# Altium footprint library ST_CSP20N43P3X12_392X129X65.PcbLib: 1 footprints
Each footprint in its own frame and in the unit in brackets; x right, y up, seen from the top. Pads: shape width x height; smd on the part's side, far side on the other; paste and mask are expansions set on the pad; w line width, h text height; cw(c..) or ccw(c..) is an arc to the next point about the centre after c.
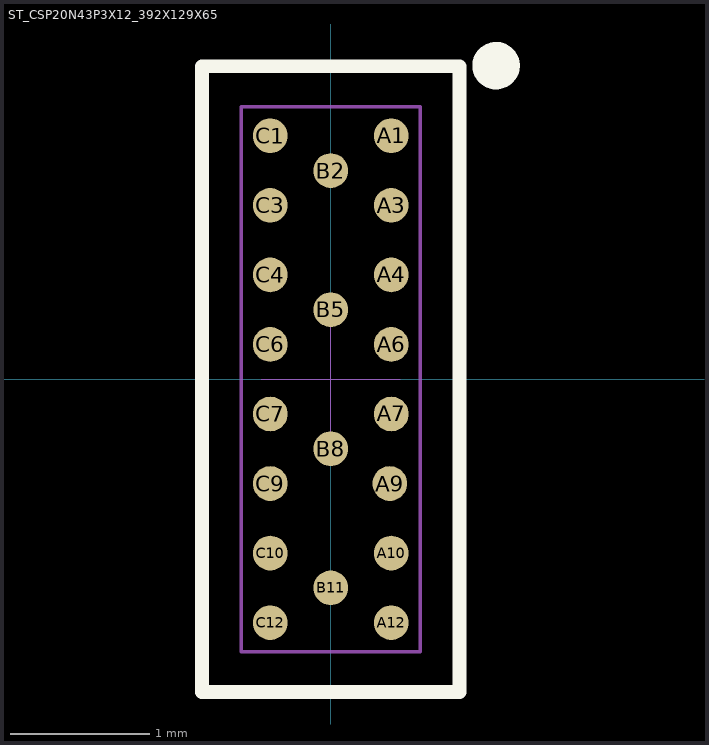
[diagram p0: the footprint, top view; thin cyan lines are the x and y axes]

## ST_CSP20N43P3X12_392X129X65 [mm] "ST_CSP20N43P3X12_392X129X65"
pads (20):
  round 0.25 smd mask+0.05: A1(0.435,1.75) A3(0.435,1.25) A4(0.435,0.75) A6(0.435,0.25) A7(0.435,-0.25) A9(0.425,-0.75) A10(0.435,-1.25) A12(0.435,-1.75) B2(0,1.5) B5(0,0.5) B8(0,-0.5) B11(0,-1.5) C1(-0.435,1.75) C3(-0.435,1.25) C4(-0.435,0.75) C6(-0.435,0.25) C7(-0.435,-0.25) C9(-0.435,-0.75) C10(-0.435,-1.25) C12(-0.435,-1.75)
Top Overlay:
  circle w0.2: c1.189,2.254 r0.071
  lines w0.1: -0.925,-2.25 -0.925,2.25 0.925,2.25 0.925,-2.25 -0.925,-2.25
Top Paste:
  rectangle: 0.27,1.585 0.6,1.915
  rectangle: -0.165,1.335 0.165,1.665
  rectangle: -0.6,1.585 -0.27,1.915
  rectangle: -0.6,1.085 -0.27,1.415
  rectangle: 0.27,1.085 0.6,1.415
  rectangle: 0.27,0.585 0.6,0.915
  rectangle: -0.165,0.335 0.165,0.665
  rectangle: -0.6,0.585 -0.27,0.915
  rectangle: -0.6,0.085 -0.27,0.415
  rectangle: 0.27,0.085 0.6,0.415
  rectangle: 0.27,-0.415 0.6,-0.085
  rectangle: -0.165,-0.665 0.165,-0.335
  rectangle: -0.6,-0.415 -0.27,-0.085
  rectangle: -0.6,-0.915 -0.27,-0.585
  rectangle: -0.6,-1.415 -0.27,-1.085
  rectangle: 0.27,-0.915 0.6,-0.585
  rectangle: 0.27,-1.415 0.6,-1.085
  rectangle: -0.165,-1.665 0.165,-1.335
  rectangle: 0.27,-1.915 0.6,-1.585
  rectangle: -0.6,-1.915 -0.27,-1.585
Mechanical 5:
  text "B2" at -0.165,1.66 h0.05
  text "B5" at -0.16,0.665 h0.05
  text "B8" at -0.16,-0.335 h0.05
  text "B11" at -0.19,-1.33 h0.05
  text "A1" at 0.705,1.755 h0.05
  text "A3" at 0.69,1.22 h0.05
  text "A4" at 0.69,0.72 h0.05
  text "A6" at 0.69,0.25 h0.05
  text "A7" at 0.705,-0.255 h0.05
  text "A9" at 0.685,-0.75 h0.05
  text "A10" at 0.715,-1.24 h0.05
  text "A12" at 0.715,-1.74 h0.05
  text "C1" at -0.74,1.74 h0.05
  text "C3" at -0.75,1.21 h0.05
  text "C4" at -0.74,0.755 h0.05
  text "C6" at -0.74,0.245 h0.05
  text "C7" at -0.74,-0.255 h0.05
  text "C9" at -0.74,-0.755 h0.05
  text "C10" at -0.755,-1.25 h0.05
  text "C12" at -0.755,-1.75 h0.05
Mechanical 6:
  lines w0.025: -0.645,-1.96 0.645,-1.96 0.645,1.96 -0.645,1.96 -0.645,-1.96
Mechanical 7:
  lines w0.025: -0.645,-1.96 -0.645,1.96 0.645,1.96 0.645,-1.96 -0.645,-1.96
Mechanical 15:
  lines w0.001: -0.5,0 0.5,0 ; 0,-0.5 0,0.5
3D body: height 0.65, standoff 0.32, extent -0.645,-1.96 0.645,1.96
